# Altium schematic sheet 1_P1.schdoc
size 429 x 307 mm; Symbol: Drawing-Symbol_A4; Device: Drawing-Symbol_A4; @Project Name: USB_FLARM_UPDATER; @Page Count: 1; @Update Date: 2026-03-08; @Create Date: 2026-02-26; @Schematic Name: Schematic1; @Page No: 1; @Page Name: P1; Company: EasyEDA.com; Version: V1.0; Page Size: A4; @Create Time: 21:30:48; @Update Time: 21:58:53; Width: 1655; Height: 1170; Region Start: 1; X Region Count: 6; Y Region Count: 4; Blade Width: 10; Title Block Position: 3; @Board Name: Board1
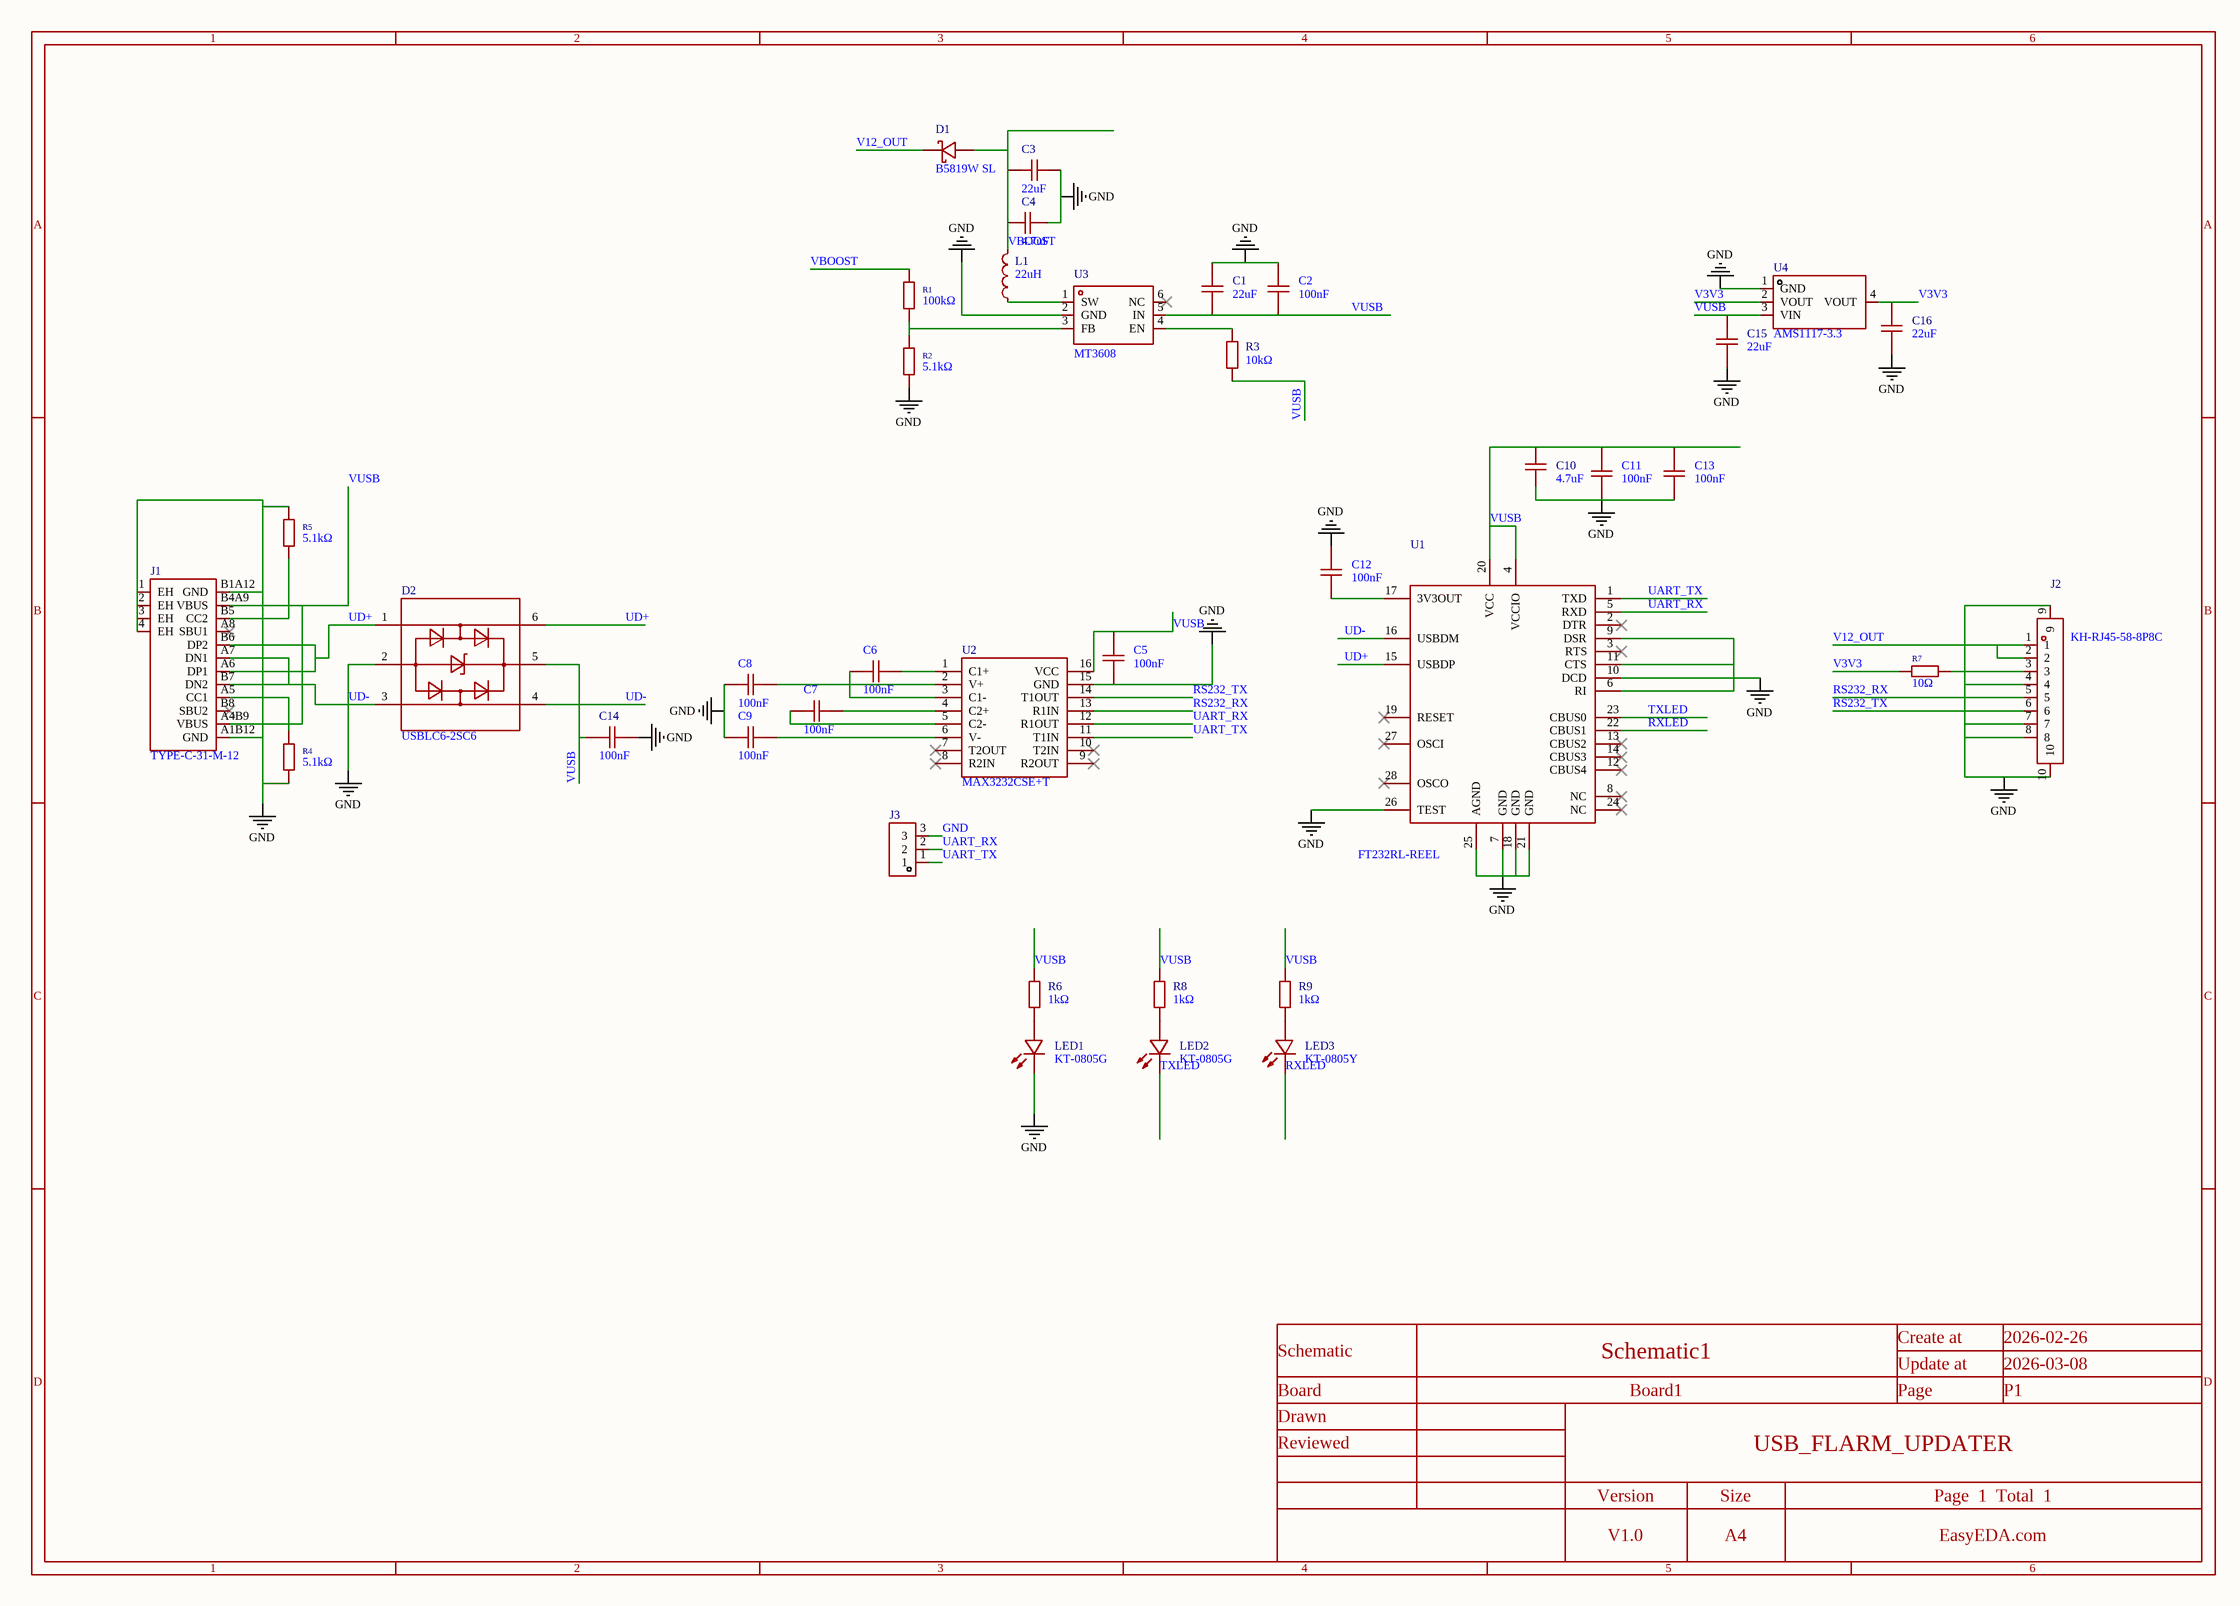
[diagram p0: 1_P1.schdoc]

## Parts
C1  22uF  [C0805]
C2  100nF  [C0402]
C3  22uF  [C0805]
C4  4.7uF  [C0805]
C5  100nF  [C0402]
C6  100nF  [C0402]
C7  100nF  [C0402]
C8  100nF  [C0402]
C9  100nF  [C0402]
C10  4.7uF  [C0805]
C11  100nF  [C0402]
C12  100nF  [C0402]
C13  100nF  [C0402]
C14  100nF  [C0402]
C15  22uF  [C0805]
C16  22uF  [C0805]
D1  B5819W SL  [SOD-123_L2.7-W1.6-LS3.7-RD-1]
D2  USBLC6-2SC6  [SOT-23-6_L2.9-W1.6-P0.95-LS2.8-BL]
J1  TYPE-C-31-M-12  [USB-C_SMD-TYPE-C-31-M-12_1]
J2  KH-RJ45-58-8P8C  [RJ45-TH_KH-RJ45-58-8P8C]
J3  (no value)  [HDR-TH_3P-P2.54-V-M]
L1  22uH  [IND-SMD_L4.0-W4.0_LQH44PN2R2MP0L]
LED1  KT-0805G  [LED0805-R-RD]
LED2  KT-0805G  [LED0805-R-RD]
LED3  KT-0805Y  [LED0805-R-RD]
R1  100kΩ  [R0402]
R2  5.1kΩ  [R0402]
R3  10kΩ  [R0402]
R4  5.1kΩ  [R0402]
R5  5.1kΩ  [R0402]
R6  1kΩ  [R0402]
R7  10Ω  [R0402]
R8  1kΩ  [R0402]
R9  1kΩ  [R0402]
U1  FT232RL-REEL  [SSOP-28_L10.2-W5.3-P0.65-LS7.8-BL]
U2  MAX3232CSE+T  [SOIC-16_L9.9-W3.9-P1.27-LS6.0-BL]
U3  MT3608  [SOT-23-6_L2.9-W1.6-P0.95-LS2.8-BL]
U4  AMS1117-3.3  [SOT-223-3_L6.5-W3.4-P2.30-LS7.0-BR]

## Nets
GND: C1.2 C2.2 C3.2 C4.2 C5.1 C8.2 C9.2 C10.1 C11.1 C12.2 C13.1 C14.2 C15.1 C16.1 D2.2 D2.3 D2.4 J1.1(EH) J1.2(EH) J1.3(EH) J1.4(EH) J1.A1B12(GND) J1.A7(DN1) J1.B1A12(GND) J1.B7(DN2) J2.4 J2.7 J2.8 J2.9 J2.10 J3.3 LED1.2(K) R2.1 R4.1 R5.1 U1.6(RI) U1.7(GND) U1.9(DSR) U1.10(DCD) U1.11(CTS) U1.16(USBDM) U1.18(GND) U1.21(GND) U1.25(AGND) U1.26(TEST) U2.15(GND) U3.2(GND) U4.1(GND)  [also labelled UD-]
RS232_RX: J2.5 U2.13(R1IN)
RS232_TX: J2.6 U2.14(T1OUT)
RXLED: LED3.2(-) U1.22(CBUS1)
TXLED: LED2.2(K) U1.23(CBUS0)
UART_RX: J3.2 U1.5(RXD) U2.12(R1OUT)
UART_TX: J3.1 U1.1(TXD) U2.11(T1IN)
UD+: D2.1 D2.6 J1.A6(DP1) J1.B6(DP2) U1.15(USBDP)
V3V3: C16.2 R7.1 U4.2(VOUT) U4.4(VOUT)
V12_OUT: D1.1(-) J2.1 J2.2
VBOOST: C3.1 C4.1 D1.2(+) L1.2 R1.2
VUSB: C1.1 C2.1 C5.2 C10.2 C11.2 C13.2 C14.1 C15.2 D2.5 J1.A4B9(VBUS) J1.B4A9(VBUS) R3.2 R6.2 R8.2 R9.2 U1.4(VCCIO) U1.20(VCC) U2.16(VCC) U3.5(IN) U4.3(VIN)
NetC6_1: C6.1 U2.1(C1+)
NetC6_2: C6.2 U2.3(C1-)
NetC7_1: C7.1 U2.4(C2+)
NetC7_2: C7.2 U2.5(C2-)
NetC8_1: C8.1 U2.2(V+)
NetC9_1: C9.1 U2.6(V-)
NetC12_1: C12.1 U1.17(3V3OUT)
NetJ1_A5: J1.A5(CC1) R4.2
NetJ1_B5: J1.B5(CC2) R5.2
NetJ2_3: J2.3 R7.2
NetL1_1: L1.1 U3.1(SW)
NetLED1_1: LED1.1(A) R6.1
NetLED2_1: LED2.1(A) R8.1
NetLED3_1: LED3.1(+) R9.1
NetR1_1: R1.1 R2.2 U3.3(FB)
NetR3_1: R3.1 U3.4(EN)

Not connected (* = marked no-connect by the designer): J1 A8(SBU1)* B8(SBU2)*; U1 2(DTR)* 3(RTS)* 8(NC)* 12(CBUS4)* 13(CBUS2)* 14(CBUS3)* 19(RESET)* 24(NC)* 27(OSCI)* 28(OSCO)*; U2 7(T2OUT)* 8(R2IN)* 9(R2OUT)* 10(T2IN)*; U3 6(NC)*

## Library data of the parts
C1 C3 C15 C16 = CL21A226MAQNNNE: Manufacturer: SAMSUNG(三星); Add into BOM: yes; Tolerance: ±20%; Voltage Rating: 25V; Temperature Coefficient: X5R
C2 C5-C9 C11-C14 = CL05B104KB54PNC: Manufacturer: SAMSUNG(三星); Add into BOM: yes; Tolerance: ±10%; Voltage Rating: 50V; Temperature Coefficient: X7R
C4 C10 = CL21A475KAQNNNE: Manufacturer: SAMSUNG(三星); Add into BOM: yes; Tolerance: ±10%; Voltage Rating: 25V; Temperature Coefficient: X5R
D1 = B5819W SL: Manufacturer: CJ(江苏长电/长晶); Symbol: B5819W_C8598; Add into BOM: yes; Voltage - Forward(Vf@If): 600mV@1A; Voltage - DC Reverse(Vr): 40V; Current - Rectified: 1A; Non-Repetitive Peak Forward Surge Current: 9A
D2 = USBLC6-2SC6_C7519: Manufacturer: ST(意法半导体); Add into BOM: yes; Polarity: Unidirectional; Reverse Stand-Off Voltage (Vrwm): 5.25V; Clamping Voltage: 17V; Peak Pulse Current (Ipp): 5A; Voltage - Breakdown: 6V; Reverse Leakage Current (Ir): 150nA; Number of Channels: 2; level of protection: IEC 61000-4-2; Type: ESD; Junction Capacitance: 3.5pF
J1 = TYPE-C-31-M-12: Manufacturer: 韩国韩荣; Add into BOM: yes; Connector Type: Type-C; Gender: Female; Number of Contacts: 16P; Number of Ports: 1; Current Rating-Power: 5A; Voltage Rating: 20V; Connect-Disconnect Life: 10,000 cycles
J2 = KH-RJ45-58-8P8C: Manufacturer: kinghelm(金航标); Add into BOM: yes; Connector Type: RJ45 Jack; Number of Ports: 1; LED: Non-LED; Shielding: Shielded; PoE: Non-PoE
J3 = HDR-M_2.54_1x3P: Symbol: PZ254V-11-03P_C2937625; Convert to PCB: yes
L1 = SMNR4020-22UH: Manufacturer: SXN(顺翔诺); Add into BOM: yes; Tolerance: ±20%; Current Rating: 1.05A; DC Resistance(DCR): 455mΩ; Type: Magnetic Shielded Inductor
LED1 LED2 = KT-0805G: Manufacturer: KENTO; Symbol: 0805G (Green); Add into BOM: yes; Illumination Color: Emerald Green; Voltage - Forward(Vf): 2.6V~3.1V; Power(Watts): 100mW; Forward Current: 5mA; Wavelength - Dominant: 513nm~528nm; Peak Wavelength: 525nm; Luminous Intensity: 430mcd; Viewing Angle: 120°
LED3 = KT-0805Y: Manufacturer: KENTO; Symbol: 17-21SUYC/TR8; Add into BOM: yes; Illumination Color: Yellow; Voltage - Forward(Vf): 1.8V~2.4V; Power(Watts): 40mW; Wavelength - Dominant: 584nm~594nm; Peak Wavelength: 596nm; Lens Color: Water Clear; Luminous Intensity: 175mcd; Viewing Angle: 120°
R1 = 0402WGF1003TCE: Manufacturer: UNI-ROYAL(厚声); Add into BOM: yes; Tolerance: ±1%; Power(Watts): 62.5mW; Voltage-Supply(Max): 50V; Temperature Coefficient: ±100ppm/℃
R2 R4 R5 = 0402WGF5101TCE: Manufacturer: UNI-ROYAL(厚声); Add into BOM: yes; Tolerance: ±1%; Power(Watts): 62.5mW; Voltage-Supply(Max): 50V; Temperature Coefficient: ±100ppm/℃
R3 = 0402WGF1002TCE: Manufacturer: UNI-ROYAL(厚声); Add into BOM: yes; Tolerance: ±1%; Power(Watts): 62.5mW; Voltage-Supply(Max): 50V; Temperature Coefficient: ±100ppm/℃
R6 R8 R9 = 0402WGF1001TCE: Manufacturer: UNI-ROYAL(厚声); Add into BOM: yes; Tolerance: ±1%; Power(Watts): 62.5mW; Voltage-Supply(Max): 50V; Temperature Coefficient: ±100ppm/℃
R7 = 0402WGF100JTCE: Manufacturer: UNI-ROYAL(厚声); Add into BOM: yes; Tolerance: ±1%; Power(Watts): 62.5mW; Voltage-Supply(Max): 50V; Temperature Coefficient: ±200ppm/℃
U1 = FT232RL-REEL: Manufacturer: FTDI(飞特帝亚); Add into BOM: yes; Applications Function: USB to UART; USB Protocol: USB 2.0; Voltage - Supply: 3.3V~5.25V; Data Rate: 3Mbps; Current - Supply: 15mA; Supply Current (Iq): 70uA
U2 = MAX3232CSE+T_C7258: Manufacturer: ADI(亚德诺)/MAXIM(美信); Add into BOM: yes; Number of Drivers: 2; Data Rate: 235Kbps; Voltage - Supply: 3V~5.5V
U3 = MT3608: Manufacturer: 西安航天民芯; Add into BOM: yes; Function: Boost; Output Type: Adjustable; Voltage - Supply: 2V~24V; Output Current: 2A; Frequency - Switching: 1.2MHz; Synchronous Rectifier: No; Number of Outputs: 1; Quiescent Current: 100uA；1.6mA; Switch tube (built-in/external): Built-in
U4 = AMS1117-3.3_C6186: Manufacturer: AMS; Add into BOM: yes; Output Type: Fixed; Voltage - Supply: 16V; Output Voltage: 3.3V; Output Current: 1A; Power Supply Rejection Ratio (PSRR): 72dB@(120Hz); Voltage Dropout: 1.1V@(800mA); standby current: 5mA; Noise: 0.003%Vout; Output Configuration: Positive; Number of Outputs: 1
